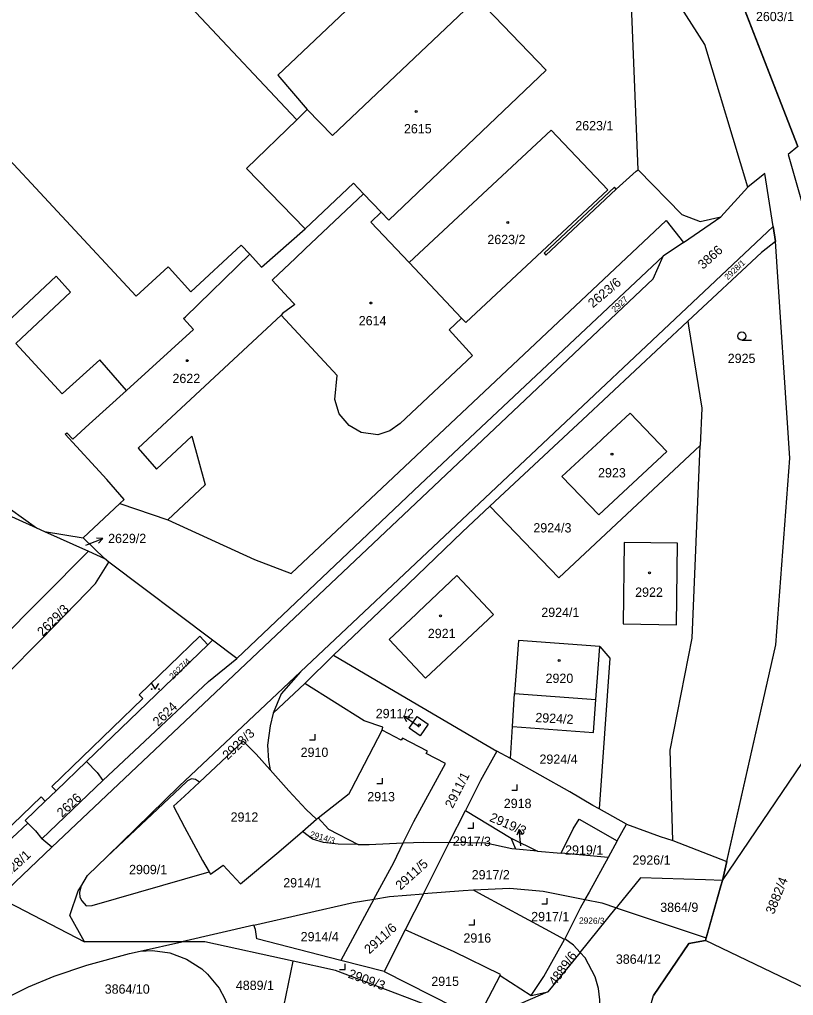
# Model space of a CAD drawing. Extents: x -527335 to -526256, y -1079142 to -1077836.
# Drawn here: x -526891.4 to -526750.1, y -1078620.2 to -1078442 of the extents above; entities that cross this region are included whole.
import ezdxf

# ---------------------------------------------------------------- set-up
doc = ezdxf.new("R2010")
doc.units = 0
for name, color, linetype in [('Hranice parcel', 7, 'Continuous'), ('Parcelní čísla', 7, 'Continuous'), ('Pop  PČ popisy', 7, 'Continuous'), ('Vnitřní kresba', 7, 'Continuous'), ('Vrstva 54', 7, 'Continuous'), ('Značky budov', 7, 'Continuous'), ('Značky kultur', 7, 'Continuous')]:
    doc.layers.add(name, color=color, linetype=linetype)

msp = doc.modelspace()

# ---------------------------------------------------------------- linework, layer by layer
at = {"layer": 'Hranice parcel'}
for p, q in [((-526749.3, -1078465.23), (-526770.17, -1078411.49)), ((-526838.85, -1078458.45), (-526840.79, -1078460.33)), ((-526825.34, -1078477.23), (-526828.58, -1078473.84)), ((-526753.77, -1078479.82), (-526753.35, -1078482.54)), ((-526770.14, -1078482.72), (-526773.85, -1078485.27)), ((-526810.68, -1078496.54), (-526820.27, -1078486.37)), ((-526906.93, -1078526.46), (-526888.33, -1078534.82)), ((-526897.02, -1078528.64), (-526888.33, -1078534.82)), ((-526879.76, -1078536.65), (-526873.08, -1078530.39)), ((-526873.08, -1078530.39), (-526864.31, -1078533.39)), ((-526888.33, -1078534.82), (-526886.82, -1078535.5)), ((-526886.82, -1078535.5), (-526879.76, -1078536.65)), ((-526886.82, -1078535.5), (-526878.8, -1078539.1)), ((-526875.87, -1078540.42), (-526879.76, -1078536.65)), ((-526763.05, -1078599.24), (-526721.31, -1078537.57)), ((-526878.8, -1078539.1), (-526875.87, -1078540.42)), ((-526875.12, -1078541.14), (-526875.87, -1078540.42)), ((-526856.15, -1078555.37), (-526875.12, -1078541.14)), ((-526856.15, -1078555.37), (-526857, -1078556.19)), ((-526851.7, -1078558.7), (-526856.15, -1078555.37)), ((-526857, -1078556.19), (-526879.18, -1078577.52)), ((-526786.16, -1078566.18), (-526785.43, -1078556.48)), ((-526834.08, -1078558.06), (-526839.29, -1078563.28)), ((-526839.29, -1078563.28), (-526845.09, -1078568.69)), ((-526801.4, -1078571.13), (-526801.02, -1078565.1)), ((-526801.02, -1078565.1), (-526786.16, -1078566.18)), ((-526801.77, -1078576.98), (-526801.4, -1078571.13)), ((-526801.77, -1078576.98), (-526804.24, -1078575.61)), ((-526879.18, -1078577.52), (-526884.72, -1078582.84)), ((-526887.33, -1078591.65), (-526876.2, -1078580.96)), ((-526884.72, -1078582.84), (-526886.71, -1078584.76)), ((-526812.92, -1078592.29), (-526809.98, -1078586.45)), ((-526809.98, -1078586.45), (-526801.63, -1078591.5)), ((-526780.55, -1078588.92), (-526785.56, -1078586.15)), ((-526839.76, -1078590.3), (-526837.18, -1078588.06)), ((-526837.18, -1078588.06), (-526836.88, -1078587.8)), ((-526782.27, -1078592), (-526780.55, -1078588.92)), ((-526885.48, -1078593.16), (-526887.33, -1078591.65)), ((-526801.63, -1078591.5), (-526796.82, -1078593.87)), ((-526800.75, -1078593.53), (-526801.63, -1078591.5)), ((-526782.27, -1078592), (-526783.92, -1078595.01)), ((-526772.12, -1078591.94), (-526762.26, -1078595.74)), ((-526796.82, -1078593.87), (-526800.75, -1078593.53)), ((-526796.82, -1078593.87), (-526792.5, -1078594.25)), ((-526783.92, -1078595.01), (-526792.5, -1078594.25)), ((-526762.26, -1078595.74), (-526763.05, -1078599.24)), ((-526817.65, -1078601.67), (-526820.97, -1078608.26)), ((-526895.17, -1078602.34), (-526879.54, -1078610.46)), ((-526826.68, -1078602.64), (-526832.73, -1078613.84)), ((-526788.16, -1078602.71), (-526788.19, -1078602.76)), ((-526789.05, -1078612.35), (-526782.42, -1078604.22)), ((-526782.41, -1078604.2), (-526782.42, -1078604.22)), ((-526848.61, -1078607.41), (-526861.78, -1078610.41)), ((-526820.97, -1078608.26), (-526824.79, -1078615.85)), ((-526861.78, -1078610.41), (-526879.54, -1078610.46)), ((-526869.37, -1078612.14), (-526861.78, -1078610.41)), ((-526791.84, -1078609.88), (-526791.91, -1078610.01)), ((-526765.99, -1078609.71), (-526766.12, -1078610.17)), ((-526747.97, -1078618.86), (-526766.12, -1078610.17)), ((-526789.05, -1078612.35), (-526794.91, -1078619.55)), ((-526843.73, -1078625.21), (-526841.41, -1078613.96)), ((-526824.79, -1078615.85), (-526832.73, -1078613.84)), ((-526803.66, -1078616.58), (-526797.97, -1078620.22)), ((-526797.97, -1078620.22), (-526794.91, -1078619.55))]:
    msp.add_line(p, q, dxfattribs=at)
for points in [[(-526758.4, -1078472.62), (-526766.27, -1078446.58), (-526780.95, -1078423.56), (-526794.44, -1078407.43), (-526800.43, -1078400.96), (-526814.56, -1078388.75), (-526829.06, -1078378.91), (-526860.51, -1078363.6), (-526886.41, -1078357.78), (-526924.51, -1078355.89), (-526949.93, -1078359.99), (-526973.92, -1078367.12), (-526999.06, -1078381.03), (-527019.7, -1078396.51), (-527044.07, -1078424.46), (-527066.65, -1078463.1), (-527068.91, -1078470.58)], [(-526840.79, -1078460.33), (-526841.89, -1078459.21), (-526874.61, -1078424.3), (-526878.19, -1078427.72), (-526880.3, -1078425.42), (-526880.87, -1078425.99), (-526891.66, -1078414.75), (-526897.96, -1078408.2), (-526900.4, -1078410.54), (-526911.2, -1078399.25), (-526900, -1078388.5), (-526889.36, -1078399.98), (-526891.93, -1078402.44), (-526885.63, -1078409.03), (-526874.72, -1078398.65), (-526868.88, -1078404.78), (-526862.16, -1078398.39), (-526849.69, -1078411.69), (-526867.72, -1078428.67), (-526857.08, -1078439.26), (-526830.69, -1078414.21), (-526818.25, -1078427.57), (-526844.26, -1078452.22), (-526838.85, -1078458.45)], [(-526838.85, -1078458.45), (-526834.26, -1078463.18), (-526807.84, -1078438.11), (-526795.26, -1078451.29), (-526823.96, -1078478.68), (-526825.34, -1078477.23)], [(-526839.26, -1078480.27), (-526849.97, -1078469.26), (-526840.79, -1078460.33)], [(-526820.27, -1078486.37), (-526794.32, -1078462.21), (-526783.99, -1078473.11), (-526809.91, -1078497.36), (-526810.68, -1078496.54)], [(-526897.29, -1078463.32), (-526870.09, -1078492.57), (-526864.29, -1078487.18), (-526864.11, -1078487.39), (-526860.13, -1078491.78), (-526850.96, -1078483.22), (-526849.35, -1078484.86)], [(-526749.3, -1078465.23), (-526751.01, -1078466.68), (-526748.62, -1078475.19)], [(-526871.89, -1078509.77), (-526876.76, -1078504.18), (-526882.89, -1078509.7), (-526883.6, -1078510.36), (-526892.11, -1078501.21), (-526882.07, -1078491.81), (-526884.74, -1078488.89), (-526907.87, -1078510.54), (-526926.56, -1078490.64), (-526928.05, -1078489.06), (-526922.69, -1078484.05), (-526921.17, -1078485.61), (-526904.09, -1078469.66)], [(-526753.77, -1078479.82), (-526755.3, -1078470.16), (-526758.4, -1078472.62)], [(-526839.26, -1078480.27), (-526830.42, -1078471.91), (-526828.58, -1078473.84)], [(-526770.14, -1078482.72), (-526763.32, -1078478.03), (-526758.4, -1078472.62)], [(-526828.58, -1078473.84), (-526839.22, -1078483.91), (-526841.07, -1078485.66), (-526845.12, -1078489.49)], [(-526864.31, -1078533.39), (-526848.5, -1078540.61), (-526841.78, -1078543.17), (-526773.33, -1078478.73), (-526770.14, -1078482.72)], [(-526825.34, -1078477.23), (-526827.25, -1078479.06), (-526820.27, -1078486.37)], [(-526849.35, -1078484.86), (-526847.19, -1078487.22), (-526839.26, -1078480.27)], [(-526840.1, -1078561.16), (-526811.64, -1078534.34), (-526753.77, -1078479.82)], [(-526753.35, -1078482.54), (-526755.93, -1078484.59), (-526769.34, -1078497.12)], [(-526762.26, -1078595.74), (-526753.29, -1078556.18), (-526750.73, -1078522.13), (-526753.35, -1078482.54)], [(-526885.48, -1078593.16), (-526816.84, -1078528.24), (-526775.71, -1078489.35), (-526773.85, -1078485.27)], [(-526871.89, -1078509.77), (-526859.62, -1078498.65), (-526861.45, -1078496.61), (-526861.12, -1078496.29), (-526849.35, -1078484.86)], [(-526773.85, -1078485.27), (-526818.22, -1078526.95), (-526851.7, -1078558.7)], [(-526845.12, -1078489.49), (-526845.25, -1078489.61), (-526841.51, -1078493.68), (-526841.15, -1078494.06), (-526843.36, -1078495.73), (-526843.65, -1078496)], [(-526843.65, -1078496), (-526869.77, -1078520.28), (-526866.37, -1078524.13), (-526859.93, -1078518.13), (-526857.53, -1078527.02), (-526864.31, -1078533.39)], [(-526810.68, -1078496.54), (-526812.93, -1078498.66), (-526808.68, -1078503.38), (-526821.91, -1078515.82), (-526823.8, -1078517.16), (-526825.95, -1078517.84), (-526829.02, -1078517.41), (-526831.23, -1078516.18), (-526833.05, -1078514), (-526833.83, -1078511.38), (-526833.41, -1078507.01), (-526843.65, -1078496)], [(-526769.34, -1078497.12), (-526788.58, -1078515.1), (-526790.3, -1078516.7), (-526805.51, -1078530.91)], [(-526769.34, -1078497.12), (-526769.21, -1078497.93), (-526766.8, -1078513), (-526767.09, -1078519.8)], [(-526873.08, -1078530.39), (-526872.28, -1078529.64), (-526875.48, -1078526), (-526883.07, -1078517.74), (-526882.77, -1078517.47), (-526881.7, -1078518.65), (-526878.67, -1078515.91), (-526871.89, -1078509.77)], [(-526779.88, -1078513.92), (-526784.89, -1078518.55), (-526785.27, -1078518.9), (-526792.39, -1078525.49), (-526785.6, -1078532.49), (-526773.2, -1078520.89), (-526779.88, -1078513.92)], [(-526767.09, -1078519.8), (-526792.89, -1078543.98), (-526805.51, -1078530.91)], [(-526772.12, -1078591.94), (-526772.6, -1078575.43), (-526768.57, -1078554.96), (-526767.09, -1078519.8)], [(-526805.51, -1078530.91), (-526810.52, -1078535.59), (-526822.1, -1078546.72), (-526834.08, -1078558.06)], [(-526878.8, -1078539.1), (-526895.62, -1078555.97), (-526900.9, -1078551.5), (-526916.27, -1078535.54)], [(-526918.14, -1078537.35), (-526918.76, -1078537.96), (-526904.45, -1078551.8), (-526894.03, -1078561.87), (-526887.38, -1078555.19), (-526885.32, -1078553.06), (-526881, -1078548.61), (-526877.52, -1078545.02), (-526875.12, -1078541.14)], [(-526771.26, -1078537.64), (-526780.99, -1078537.49), (-526781.14, -1078552.39), (-526771.41, -1078552.54), (-526771.26, -1078537.64)], [(-526823.91, -1078555.25), (-526817.29, -1078562.29), (-526804.86, -1078550.67), (-526811.52, -1078543.55), (-526818.58, -1078550.22), (-526818.96, -1078550.58), (-526823.91, -1078555.25)], [(-526884.72, -1078582.84), (-526885.5, -1078582.04), (-526868.86, -1078566.03), (-526869.58, -1078565.31), (-526858.51, -1078554.63), (-526857, -1078556.19)], [(-526785.43, -1078556.48), (-526800.29, -1078555.4), (-526801.02, -1078565.1)], [(-526785.43, -1078556.48), (-526783.61, -1078558.62), (-526785.56, -1078586.15)], [(-526876.2, -1078580.96), (-526869.49, -1078574.69), (-526856.88, -1078562.91), (-526851.7, -1078558.7)], [(-526834.08, -1078558.06), (-526819.73, -1078566.52), (-526804.24, -1078575.61)], [(-526875.42, -1078594.83), (-526862.23, -1078582.01), (-526840.1, -1078561.16)], [(-526840.1, -1078561.16), (-526843.61, -1078565.14), (-526845.09, -1078568.69)], [(-526825.2, -1078571.8), (-526825.03, -1078571.25), (-526828.48, -1078570.07), (-526839.29, -1078563.28)], [(-526801.4, -1078571.13), (-526786.56, -1078572.21), (-526786.16, -1078566.18)], [(-526845.09, -1078568.69), (-526845.65, -1078570.98), (-526846.11, -1078574.51), (-526845.94, -1078577.33), (-526845.63, -1078579.02)], [(-526818.82, -1078569.27), (-526816.76, -1078570.67), (-526818.23, -1078572.81), (-526820.28, -1078571.39), (-526818.82, -1078569.27)], [(-526836.88, -1078587.8), (-526831.2, -1078583.35), (-526830.8, -1078582.53), (-526825.2, -1078571.8)], [(-526821.32, -1078592.38), (-526819.4, -1078588.47), (-526813.61, -1078577.89), (-526817.15, -1078576.02), (-526816.93, -1078575.61), (-526821.48, -1078573.22), (-526821.7, -1078573.63), (-526825.2, -1078571.8)], [(-526845.63, -1078579.02), (-526848.19, -1078576.15), (-526850.56, -1078573.79), (-526858.57, -1078581.3)], [(-526804.24, -1078575.61), (-526807.22, -1078580.97), (-526809.98, -1078586.45)], [(-526879.18, -1078577.52), (-526877.26, -1078579.54), (-526876.2, -1078580.96)], [(-526785.56, -1078586.15), (-526786.71, -1078585.52), (-526790.88, -1078583.04), (-526801.77, -1078576.98)], [(-526845.63, -1078579.02), (-526842.21, -1078582.84), (-526839.09, -1078586.26), (-526837.18, -1078588.06)], [(-526858.57, -1078581.3), (-526859.26, -1078580.78), (-526860.01, -1078580.69), (-526860.74, -1078581.06), (-526862.08, -1078582.31), (-526875.42, -1078594.83)], [(-526858.57, -1078581.3), (-526861.3, -1078583.86), (-526863.29, -1078585.66), (-526861.26, -1078589.47), (-526858, -1078595.58), (-526856.77, -1078597.64)], [(-526886.71, -1078584.76), (-526887.47, -1078583.94), (-526927.4, -1078622.44), (-526930.86, -1078618.91), (-526934.27, -1078622.19), (-526943.73, -1078612.76), (-526944.56, -1078613.6), (-526956.67, -1078601.43), (-526954.52, -1078597.86), (-526954.82, -1078597.51)], [(-526886.71, -1078584.76), (-526890.36, -1078588.27), (-526889.91, -1078588.74)], [(-526889.91, -1078588.74), (-526892.73, -1078591.42), (-526896.25, -1078594.77), (-526901.11, -1078599.39)], [(-526889.91, -1078588.74), (-526888.52, -1078590.18), (-526887.33, -1078591.65)], [(-526836.88, -1078587.8), (-526835, -1078589.83), (-526829.55, -1078592.63)], [(-526792.5, -1078594.25), (-526790.29, -1078589.81), (-526789.21, -1078588.02), (-526782.27, -1078592)], [(-526780.55, -1078588.92), (-526774.44, -1078591.19), (-526772.12, -1078591.94)], [(-526856.77, -1078597.64), (-526856.53, -1078598.05), (-526854.22, -1078596.45), (-526851.03, -1078599.85), (-526844.03, -1078594), (-526839.76, -1078590.3)], [(-526829.55, -1078592.63), (-526833.19, -1078592.62), (-526835.9, -1078592.29), (-526837.89, -1078591.66), (-526839.76, -1078590.3)], [(-526829.55, -1078592.63), (-526827.54, -1078592.63), (-526821.32, -1078592.38)], [(-526826.68, -1078602.64), (-526823.07, -1078595.95), (-526821.32, -1078592.38)], [(-526821.32, -1078592.38), (-526817.59, -1078592.23), (-526812.92, -1078592.29)], [(-526817.65, -1078601.67), (-526815.44, -1078597.3), (-526812.92, -1078592.29)], [(-526800.75, -1078593.53), (-526801.5, -1078593.46), (-526806.23, -1078592.39), (-526812.92, -1078592.29)], [(-526895.17, -1078602.34), (-526893.54, -1078600.8), (-526885.48, -1078593.16)], [(-526880.23, -1078600.36), (-526879.01, -1078598.32), (-526875.42, -1078594.83)], [(-526783.92, -1078595.01), (-526787.39, -1078601.34), (-526788.16, -1078602.71)], [(-526880.23, -1078600.36), (-526880.46, -1078601.41), (-526880.38, -1078602.26), (-526880.06, -1078602.95), (-526879.25, -1078603.85), (-526878.13, -1078603.81), (-526856.77, -1078597.64)], [(-526763.05, -1078599.24), (-526766.12, -1078599.14), (-526777.98, -1078598.77), (-526782.2, -1078603.94), (-526782.41, -1078604.2)], [(-526763.05, -1078599.24), (-526763.31, -1078600.18), (-526765.99, -1078609.71)], [(-526879.54, -1078610.46), (-526882.22, -1078605.6), (-526880.7, -1078601.14), (-526880.23, -1078600.36)], [(-526826.68, -1078602.64), (-526823.82, -1078602.17), (-526817.65, -1078601.67)], [(-526808.5, -1078601.01), (-526810.36, -1078601.09), (-526817.65, -1078601.67)], [(-526788.19, -1078602.76), (-526795.78, -1078601.25), (-526801.89, -1078600.72), (-526808.5, -1078601.01)], [(-526791.91, -1078610.01), (-526795.37, -1078608.1), (-526806.84, -1078601.9), (-526808.5, -1078601.01)], [(-526848.61, -1078607.41), (-526830.48, -1078603.27), (-526826.68, -1078602.64)], [(-526788.19, -1078602.76), (-526789.04, -1078604.26), (-526791.84, -1078609.88)], [(-526788.16, -1078602.71), (-526785.04, -1078603.32), (-526782.41, -1078604.2)], [(-526782.42, -1078604.22), (-526767.5, -1078609.21), (-526765.99, -1078609.71)], [(-526832.73, -1078613.84), (-526848.05, -1078609.89), (-526848.31, -1078608.19), (-526848.61, -1078607.41)], [(-526803.66, -1078616.58), (-526803.57, -1078616.4), (-526812.02, -1078612.24), (-526820.97, -1078608.26)], [(-526841.41, -1078613.96), (-526857.54, -1078610.4), (-526861.78, -1078610.41)], [(-526797.97, -1078620.22), (-526795.67, -1078616.76), (-526791.91, -1078610.01)], [(-526789.05, -1078612.35), (-526790.25, -1078611.01), (-526791.84, -1078609.88)], [(-526766.12, -1078610.17), (-526769.16, -1078610.73), (-526775.66, -1078620.23)], [(-526921.59, -1078644.68), (-526911.97, -1078635.42), (-526903.16, -1078627.64), (-526896.85, -1078622.64), (-526893.43, -1078620.48), (-526889.76, -1078618.63), (-526885.07, -1078616.68), (-526879.09, -1078614.67), (-526871.32, -1078612.59), (-526869.37, -1078612.14)], [(-526869.37, -1078612.14), (-526867.13, -1078612.03), (-526863.95, -1078612.46), (-526860.92, -1078613.57), (-526858.13, -1078615.36), (-526857.06, -1078616.32), (-526854.94, -1078618.9), (-526853.89, -1078620.81), (-526853.48, -1078621.91), (-526853.17, -1078623.18)], [(-526789.19, -1078637.84), (-526785.84, -1078625.99), (-526785.42, -1078623.83), (-526785.41, -1078621.01), (-526785.67, -1078618.95), (-526786.3, -1078616.83), (-526788.13, -1078613.38), (-526789.05, -1078612.35)], [(-526819.27, -1078621.16), (-526833.71, -1078615.66), (-526841.41, -1078613.96)], [(-526824.79, -1078615.85), (-526807.79, -1078624.46), (-526803.66, -1078616.58)], [(-526794.91, -1078619.55), (-526808.25, -1078625.35), (-526819.27, -1078621.16)]]:
    msp.add_lwpolyline(points, dxfattribs=at)
at = {"layer": 'Pop  PČ popisy'}
for p, q in [((-526879.02, -1078537.88), (-526876.22, -1078536.8)), ((-526876.22, -1078536.8), (-526877.33, -1078536.7)), ((-526876.22, -1078536.8), (-526876.97, -1078537.63)), ((-526879.31, -1078537.99), (-526879.02, -1078537.88)), ((-526818.8, -1078570.92), (-526821.26, -1078569.2)), ((-526821.26, -1078569.2), (-526820.15, -1078569.36)), ((-526821.26, -1078569.2), (-526820.72, -1078570.18)), ((-526818.4, -1078571.21), (-526818.8, -1078570.92)), ((-526800.16, -1078589.92), (-526800.56, -1078590.96)), ((-526799.85, -1078592.9), (-526800.16, -1078589.92)), ((-526800.16, -1078589.92), (-526799.56, -1078590.86))]:
    msp.add_line(p, q, dxfattribs=at)
at = {"layer": 'Vnitřní kresba'}
for p, q in [((-526778.46, -1078469.48), (-526779.62, -1078439.41)), ((-526782.46, -1078473.01), (-526778.8, -1078469.74)), ((-526778.8, -1078469.74), (-526778.46, -1078469.48)), ((-526778.46, -1078469.48), (-526770.43, -1078477.62)), ((-526782.77, -1078472.66), (-526795.59, -1078484.71)), ((-526795.28, -1078485.04), (-526782.46, -1078473.01)), ((-526782.46, -1078473.01), (-526782.77, -1078472.66)), ((-526770.43, -1078477.62), (-526767.11, -1078478.91)), ((-526767.11, -1078478.91), (-526763.32, -1078478.03)), ((-526795.59, -1078484.71), (-526795.28, -1078485.04))]:
    msp.add_line(p, q, dxfattribs=at)
at = {"layer": 'Vrstva 54'}
for points in [[(-526770.17, -1078411.49), (-526749.3, -1078465.23), (-526751.01, -1078466.68), (-526748.62, -1078475.19), (-526748.09, -1078477.09), (-526743.04, -1078478.19), (-526743.27, -1078484.77), (-526740.46, -1078509.15), (-526740.51, -1078529.65), (-526721.31, -1078537.57), (-526697.27, -1078508.97)], [(-526703.39, -1078543.02), (-526715.41, -1078561.03), (-526728.83, -1078581.13), (-526744.33, -1078607.7), (-526747.97, -1078618.86), (-526766.12, -1078610.17), (-526763.31, -1078600.18), (-526763.05, -1078599.24), (-526753.29, -1078556.18), (-526750.73, -1078522.13), (-526753.35, -1078482.54), (-526753.77, -1078479.82), (-526755.3, -1078470.16), (-526758.4, -1078472.62), (-526766.27, -1078446.58), (-526780.95, -1078423.56)], [(-526796.68, -1078693.11), (-526790.82, -1078672.37), (-526797.07, -1078670.6), (-526787.88, -1078638.05), (-526781.26, -1078639.92), (-526775.66, -1078620.23), (-526769.16, -1078610.73), (-526766.12, -1078610.17)]]:
    msp.add_lwpolyline(points, dxfattribs=at)
at = {"layer": 'Značky budov'}
for centre in [(-526818.99, -1078458.82), (-526802.26, -1078479.07), (-526827.23, -1078493.79), (-526860.77, -1078504.32), (-526783.21, -1078521.38), (-526776.36, -1078543.05), (-526814.54, -1078550.91), (-526792.88, -1078559.07), (-526818.39, -1078570.82)]:
    msp.add_circle(centre, 0.175, dxfattribs=at)
at = {"layer": 'Značky kultur'}
for p, q in [((-526759.49, -1078500.58), (-526757.74, -1078500.58)), ((-526837.43, -1078573.54), (-526837.43, -1078572.54)), ((-526838.43, -1078573.54), (-526837.43, -1078573.54)), ((-526826.15, -1078581.52), (-526825.15, -1078581.52)), ((-526825.15, -1078581.52), (-526825.15, -1078580.52)), ((-526800.53, -1078582.71), (-526800.53, -1078581.71)), ((-526801.53, -1078582.71), (-526800.53, -1078582.71)), ((-526808.53, -1078589.65), (-526808.53, -1078588.65)), ((-526809.53, -1078589.65), (-526808.53, -1078589.65)), ((-526796.04, -1078603.48), (-526795.04, -1078603.48)), ((-526795.04, -1078603.48), (-526795.04, -1078602.48)), ((-526808.33, -1078607.34), (-526808.33, -1078606.34)), ((-526809.33, -1078607.34), (-526808.33, -1078607.34)), ((-526832.95, -1078615.46), (-526831.95, -1078615.46)), ((-526831.95, -1078615.46), (-526831.95, -1078614.46))]:
    msp.add_line(p, q, dxfattribs=at)
msp.add_lwpolyline([(-526867.28, -1078563.28), (-526866.61, -1078564.29), (-526865.94, -1078563.28)], dxfattribs=at)
for centre, radius in [((-526759.49, -1078499.83), 0.75), ((-526867.28, -1078564.29), 0.067), ((-526865.94, -1078564.29), 0.067)]:
    msp.add_circle(centre, radius, dxfattribs=at)

# ---------------------------------------------------------------- texts
at = {"layer": 'Parcelní čísla'}
for s, p in [('2603/1', (-526756.92, -1078442.33)), ('2623/1', (-526789.91, -1078462.26)), ('2615', (-526821.2, -1078462.82)), ('2623/2', (-526805.97, -1078483.04)), ('2614', (-526829.46, -1078497.86)), ('2925', (-526762.07, -1078504.75)), ('2622', (-526863.48, -1078508.41)), ('2923', (-526785.75, -1078525.64)), ('2924/3', (-526797.57, -1078535.69)), ('2629/2', (-526875.23, -1078537.63)), ('2922', (-526778.98, -1078547.44)), ('2924/1', (-526796.12, -1078551.12)), ('2921', (-526816.84, -1078554.98)), ('2920', (-526795.34, -1078563.16)), ('2911/2', (-526826.35, -1078569.6)), ('2910', (-526840.07, -1078576.67)), ('2924/4', (-526796.45, -1078577.93)), ('2913', (-526827.9, -1078584.77)), ('2918', (-526802.97, -1078586.01)), ('2912', (-526852.86, -1078588.49)), ('2919/1', (-526791.77, -1078594.52)), ('2926/1', (-526779.47, -1078596.34)), ('2909/1', (-526871.4, -1078598.08)), ('2917/2', (-526808.83, -1078599.03)), ('2914/1', (-526843.25, -1078600.5)), ('3864/9', (-526774.4, -1078604.97)), ('2917/1', (-526797.97, -1078606.67)), ('2914/4', (-526840.06, -1078610.33)), ('2916', (-526810.34, -1078610.58)), ('3864/12', (-526782.5, -1078614.44)), ('4889/1', (-526851.9, -1078619.22)), ('2915', (-526816.21, -1078618.49)), ('3864/10', (-526875.85, -1078619.9))]:
    msp.add_text(s, height=1.7, dxfattribs=at).set_placement(p)
for s, height, rotation, p in [('3866', 1.7, 42, (-526766.59, -1078487.74)), ('2928/1', 1.1, 43, (-526762.06, -1078489.65)), ('2623/6', 1.7, 39.9875, (-526786.71, -1078494.77)), ('2927', 1.14, 43, (-526782.66, -1078495.59)), ('2629/3', 1.7, 45, (-526887.17, -1078554.76)), ('2627/4', 1.139, 44, (-526863.4, -1078562.59)), ('2624', 1.7, 44, (-526866.1, -1078571.2)), ('2924/2', 1.7, 357, (-526797.24, -1078570.3)), ('2928/3', 1.7, 43, (-526853.4, -1078577.3)), ('2911/1', 1.7, 63, (-526812.31, -1078586.19)), ('2626', 1.7, 43, (-526883.63, -1078587.8)), ('2919/3', 1.7, 337, (-526805.71, -1078588.34)), ('2914/3', 1.139, 344, (-526838.48, -1078591.27)), ('2917/3', 1.7, 359, (-526812.29, -1078592.84)), ('2628/1', 1.7, 43, (-526894.29, -1078599.51)), ('2911/5', 1.7, 42, (-526821.82, -1078601.08)), ('3882/4', 1.7, 68, (-526753.66, -1078605.52)), ('2911/6', 1.7, 42, (-526827.52, -1078612.75)), ('2926/3', 1.139, 359, (-526789.24, -1078607.1)), ('4889/6', 1.7, 54, (-526793.57, -1078618.58)), ('2909/3', 1.7, 340, (-526831.54, -1078616.93))]:
    msp.add_text(s, height=height, rotation=rotation, dxfattribs=at).set_placement(p)

doc.saveas('drawing.dxf')
